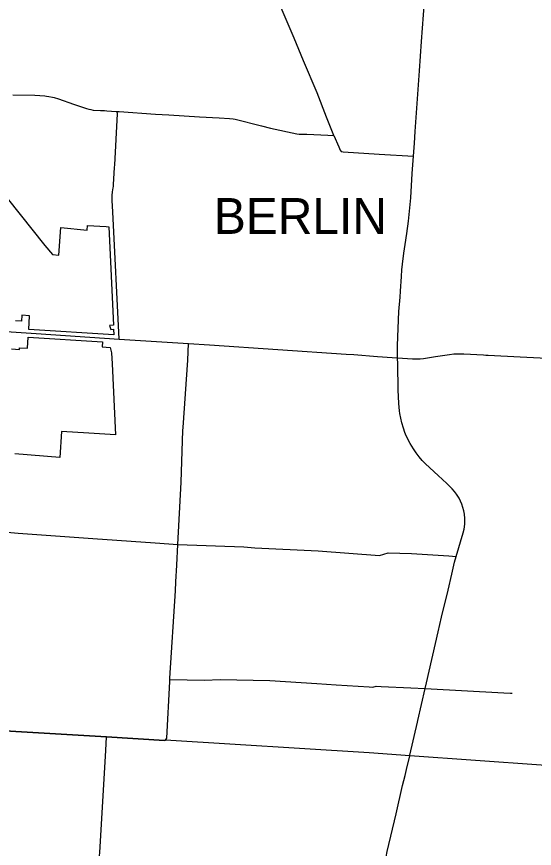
# Model space of a CAD drawing. Extents: x 1729596 to 1934326, y 644115 to 911751.
# Drawn here: x 1822891 to 1835895, y 803658 to 824548 of the extents above; entities that cross this region are included whole.
import ezdxf

# ---------------------------------------------------------------- set-up
doc = ezdxf.new("R2010")
doc.units = 0
for name, color, linetype in [('GM_X_Corporation', 7, 'Continuous'), ('GM_X_County_Road', 7, 'Continuous'), ('GM_X_Township', 7, 'Continuous'), ('GM_X_Township_Road', 7, 'Continuous'), ('GM_X_Township_Text', 7, 'Continuous')]:
    doc.layers.add(name, color=color, linetype=linetype)

msp = doc.modelspace()

# ---------------------------------------------------------------- linework, layer by layer
at = {"layer": 'GM_X_Corporation'}
for points in [[(1822355, 820361), (1823597, 818799), (1823790, 818570), (1823953, 818559), (1824004, 819253), (1824662, 819185), (1824669, 819305), (1825142, 819273), (1825203, 819269), (1825322, 816796), (1825222, 816791), (1825257, 816693), (1825327, 816696), (1825334, 816556), (1823195, 816692), (1823214, 817036), (1823021, 817048), (1823013, 816898), (1822864, 816908)], [(1822764, 816201), (1822961, 816188), (1822964, 816233), (1823161, 816221), (1823178, 816495), (1825044, 816377), (1825036, 816251), (1825240, 816235), (1825272, 816107), (1825289, 815828), (1825372, 814048), (1824702, 814085), (1824021, 814132), (1823980, 813477), (1822844, 813570)]]:
    msp.add_lwpolyline(points, dxfattribs=at)
at = {"layer": 'GM_X_County_Road'}
for points in [[(1834143, 812015), (1834139, 812054), (1834124, 812138), (1834075, 812302), (1834002, 812457), (1833942, 812552), (1833889, 812623), (1833831, 812690), (1833694, 812820), (1833478, 813020), (1833162, 813314), (1833078, 813403), (1832999, 813495), (1832925, 813592), (1832856, 813693), (1832774, 813828), (1832679, 814020), (1832645, 814102), (1832604, 814215), (1832566, 814343), (1832538, 814463), (1832516, 814584), (1832508, 814645), (1832492, 814829), (1832476, 815177), (1832464, 815817), (1832460, 815979), (1832454, 816292), (1832494, 817138), (1832523, 817499), (1832533, 817655), (1832557, 818019), (1832570, 818189), (1832583, 818334), (1832618, 818604), (1832651, 818829), (1832693, 819102), (1832736, 819407), (1832789, 819993), (1832829, 820607), (1832863, 821044), (1832886, 821374), (1832904, 821666), (1833012, 823190), (1833063, 823927), (1833158, 825274)], [(1822793, 822586), (1823349, 822572), (1823598, 822559), (1823641, 822554), (1823701, 822546), (1823794, 822525), (1823833, 822514), (1823943, 822480), (1824317, 822351), (1824572, 822264), (1824650, 822239), (1824703, 822223), (1824754, 822212), (1824817, 822203), (1825000, 822190), (1825095, 822188), (1825160, 822183)], [(1825160, 822183), (1825395, 822168), (1825420, 822166), (1825468, 822164), (1826380, 822102), (1826713, 822081), (1827481, 822035), (1827979, 822005), (1828241, 821988), (1828328, 821980), (1828376, 821970), (1829043, 821807), (1829269, 821745), (1829930, 821604), (1829991, 821596), (1830183, 821593), (1830707, 821568), (1830861, 821562), (1830987, 821277), (1831021, 821195), (1831043, 821164), (1831094, 821154), (1832000, 821097), (1832863, 821044)], [(1825464, 816451), (1825308, 819646), (1825294, 819934), (1825289, 820059), (1825298, 820149), (1825316, 820244), (1825321, 820280), (1825325, 820329), (1825352, 820760), (1825357, 820824), (1825422, 822106), (1825420, 822166)], [(1821800, 816689), (1821867, 816685), (1821902, 816683), (1822499, 816646), (1823384, 816589), (1825464, 816451)], [(1825464, 816451), (1827210, 816341), (1827734, 816305), (1831166, 816072), (1831357, 816058), (1831958, 816015)], [(1831958, 816015), (1832323, 815989), (1832460, 815979), (1832837, 815953), (1832930, 815950), (1833024, 815953), (1833112, 815962), (1833413, 816008), (1833762, 816064), (1833870, 816076), (1833979, 816082), (1834125, 816080), (1834617, 816051), (1834676, 816048), (1834735, 816046), (1835535, 816000), (1836888, 815933), (1838141, 815859), (1838366, 815848), (1838544, 815828), (1839093, 815806), (1839372, 815780)], [(1833929, 810990), (1834110, 811586), (1834129, 811671), (1834146, 811800), (1834150, 811909), (1834147, 811973), (1834143, 812015)], [(1818834, 811875), (1818898, 811871), (1820200, 811779), (1821551, 811700), (1822928, 811578), (1824804, 811444), (1826371, 811335), (1826943, 811293), (1828599, 811230), (1828871, 811205), (1830463, 811131), (1832006, 811013), (1832221, 811077), (1832807, 811061), (1833745, 811003), (1833929, 810990)], [(1833153, 807676), (1833153, 807676), (1833183, 807819), (1833482, 809095), (1833563, 809462), (1833726, 810146), (1833823, 810547), (1833891, 810845), (1833929, 810990)], [(1832766, 805999), (1832958, 806827), (1832968, 806868), (1833153, 807676)], [(1831618, 801105), (1831725, 801561), (1831782, 801810), (1831838, 802029), (1831953, 802532), (1832071, 803028), (1832169, 803448), (1832199, 803580), (1832422, 804522), (1832586, 805234), (1832650, 805492), (1832684, 805641), (1832763, 805986), (1832766, 805999)]]:
    msp.add_lwpolyline(points, dxfattribs=at)
at = {"layer": 'GM_X_Township'}
msp.add_lwpolyline([(1837716, 805633), (1832763, 805986), (1831742, 806059), (1826634, 806376), (1826602, 806370), (1825150, 806460), (1820453, 806733), (1819657, 806793), (1819325, 806814), (1819232, 806820), (1819101, 806829), (1818544, 806864), (1818726, 809558), (1818800, 810798), (1818859, 811418), (1818898, 811871), (1818966, 812859), (1819169, 816826), (1819403, 820562), (1819571, 823253), (1819973, 830336)], dxfattribs=at)
at = {"layer": 'GM_X_Township_Road'}
for points in [[(1830861, 821562), (1830675, 822019), (1830437, 822637), (1830098, 823434), (1829858, 824006), (1829489, 824884), (1829338, 825214), (1829276, 825381), (1829272, 825394), (1829293, 825885), (1829337, 826657), (1829333, 826743)], [(1826943, 811293), (1827025, 812853), (1827068, 814151), (1827071, 814228), (1827188, 815919), (1827210, 816341)], [(1826634, 806376), (1826663, 806429), (1826736, 807853), (1826739, 807902), (1826741, 807936), (1826878, 810126), (1826891, 810353), (1826913, 810774), (1826943, 811293)], [(1826739, 807902), (1827610, 807886), (1828001, 807902), (1829252, 807875), (1830428, 807799), (1830917, 807766), (1831747, 807711), (1831834, 807709), (1831924, 807730), (1832046, 807721), (1832789, 807693), (1833153, 807676), (1835124, 807566), (1835293, 807558), (1835306, 807557), (1835338, 807552)], [(1819676, 806703), (1819803, 806721), (1819894, 806734), (1820004, 806746), (1820092, 806749), (1820453, 806733), (1825150, 806460), (1826602, 806370), (1826634, 806376)], [(1824880, 801622), (1824918, 802376), (1824972, 803474), (1824977, 803552), (1825131, 806119), (1825150, 806460)]]:
    msp.add_lwpolyline(points, dxfattribs=at)

# ---------------------------------------------------------------- texts
at = {"layer": 'GM_X_Township_Text'}
msp.add_text('BERLIN', height=900, rotation=0, dxfattribs=at).set_placement((1827845, 819091))

doc.saveas('drawing.dxf')
